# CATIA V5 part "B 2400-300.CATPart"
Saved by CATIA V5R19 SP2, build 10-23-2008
Part number: B 2400-300
Bounding box of the stored display mesh (mm): x -37.351 to 37.351, y -37.351 to 37.351, z 0 to 710
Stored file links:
  C:\Users\Bora\Desktop\3D Katı model\B serisi\B 2400\B 2400-300.CATPart
  C:\Program Files\Dassault Systemes\B19\intel_a\reffiles\standard\MetricThickPitch.txt
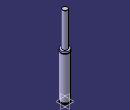
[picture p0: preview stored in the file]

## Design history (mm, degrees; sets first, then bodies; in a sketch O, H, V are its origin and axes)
Body1 (main body)
  Sketch1 on yz-plane, origin (0, 0, 0), H (0, 1, 0), V (0, 0, 1)
    point P3 (22.5, 709)
    point P5 (22.5, 709)
    point P10 (37.5, 386.5)
    point P11 (37.5, 391.5)
    point P13 (37.5, 391.5)
    point P14 (37.5, 386.5)
    line L1 (37.5, 0) -> (37.5, 8)
    line L2 (22.5, 709) -> (22.5, 407)
    arc A1 centre (21.5, 709) radius 1 from (22.5, 709) to (21.5, 710) ccw
    line L3 (33.5, 13) -> (33.5, 8)
    line L4 (37.5, 13) -> (37.5, 386.5)
    line L5 (37.5, 391.5) -> (37.5, 407)
    arc A2 centre (37.5, 389) radius 2.5 from (37.5, 391.5) to (37.5, 386.5) ccw
    line L6 (21.5, 710) -> (0, 710)
    point P15 (0, 710)
    line L7 (22.5, 407) -> (37.5, 407)
    line L8 (0, 0) -> (37.5, 0)
    line L9 (33.5, 13) -> (37.5, 13)
    line L10 (33.5, 8) -> (37.5, 8)
    coincidence: P15 V, P3 P5, P10 P14, P11 P13
    tangency: L6 A1
    horizontal: L7 H, L8 H, L9 H, L10 H
  Shaft1: profile Sketch1, axis Sketch1.V, angle 360
  Sketch2 on face of Shaft1 from Sketch1.L8, origin (0, 0, 0), H (1, 0, 0), V (0, -1, 0)
    point P1 (20, 0)
    distance P1 V = 20
  Hole1: placed by Sketch2, at (20, 0, 0) direction (0, 0, 1), diameter 6.647, depth 13, threaded "M8", thread diameter 8, thread depth 13, pitch 1.25
  CircPattern1: of Hole1, instances 4, angular step 90, axis from xy-plane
